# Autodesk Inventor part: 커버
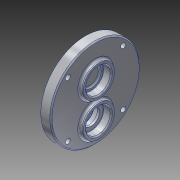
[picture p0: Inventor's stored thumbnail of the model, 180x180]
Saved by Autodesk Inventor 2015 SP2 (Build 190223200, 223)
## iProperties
Created: 2015-06
Part Number: 커버
Material: 알루미늄 6061
Document SubType Name: Modeling
Designer: AMC
Mass: 113.485 g
Surface Area: 144.875 cm^2
Volume: 42.0316 cm^3
Density: 2.7 g/cm^3
Appearance: 알루미늄 - 평지
Author: AMC
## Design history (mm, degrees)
sketch "스케치1"
  geometry: C1 r 40 at (0, 0); 1 further point
  constraints: 1 centre point, 1 coincident
  dimensions: "d0" = 80 diameter of C1
extrude "돌출1" new body sketch "스케치1" distance "d1" = 9; taper "d2" = 0 deg
sketch "스케치2"
  geometry: C1 r 14 at (20, 0); C2 r 14 at (-11, 0); 1 further point
  constraints: 2 centre point, 2 horizontal alignment
  dimensions: "d3" = 28 diameter of C1; "d4" = 20 distance of C1.centre point (0, 0); "d5" = 28 diameter of C2; "d6" = 11 distance of C2.centre point (0, 0)
extrude "돌출2" join sketch "스케치2" distance "d7" = 3; taper "d8" = 0 deg
sketch "스케치3"
  geometry: C1 r 15 at (-20, 0); 1 further point
  constraints: 1 centre point, 1 horizontal alignment
  dimensions: "d9" = 30 diameter of C1; "d10" = 20 distance of C1.centre point (0, 0)
extrude "돌출3" join sketch "스케치3" distance "d11" = 4; taper "d12" = 0 deg
hole "구멍1" diameter "d15" = 15; stored, may be unused: countersink angle "d19" = 90 deg, drill point angle "d21" = 118 deg; dims "d13" = 10, "d14" = 10, "d16" = 6, "d17" = 22, "d18" = 7, "d20" = 8
hole "구멍2" diameter "d24" = 22; stored, may be unused: countersink angle "d28" = 90 deg, drill point angle "d30" = 0 deg; dims "d22" = 10, "d23" = 10, "d25" = 6, "d26" = 22, "d27" = 7, "d29" = 7
hole "구멍3" diameter "d33" = 18; stored, may be unused: countersink angle "d37" = 90 deg, drill point angle "d39" = 0 deg; dims "d31" = 10, "d32" = 10, "d34" = 6, "d35" = 22, "d36" = 7, "d38" = 8
sketch "스케치4"
  geometry: L1 (0, 0)-(24.749, 24.749); L2 (0, 0)-(35, 0); 1 further point
  constraints: 4 end point, 1 coincident, 1 equal length, 1 horizontal
  dimensions: "d40" = 35 distance of L1.start L1.end; "d41" = 45 deg angle of L2 L1
hole "구멍4" sketch "스케치4" at (24.749, 24.749) diameter "d42" = 4.5; stored, may be unused: countersink angle "d46" = 90 deg, drill point angle "d48" = 0 deg; dims "d43" = 6, "d44" = 8, "d45" = 4.4, "d47" = 8
fillet "모깎기1" dims "d52" = 2
fillet "모깎기2" dims "d53" = 0.3
chamfer "모따기1" distance "d54" = 1; stored, may be unused: second distance "d55" = 2, angle "d56" = 45 deg
node "솔리드1"
pattern_circular "원형 패턴1" dims angle "d50" = 360 deg
